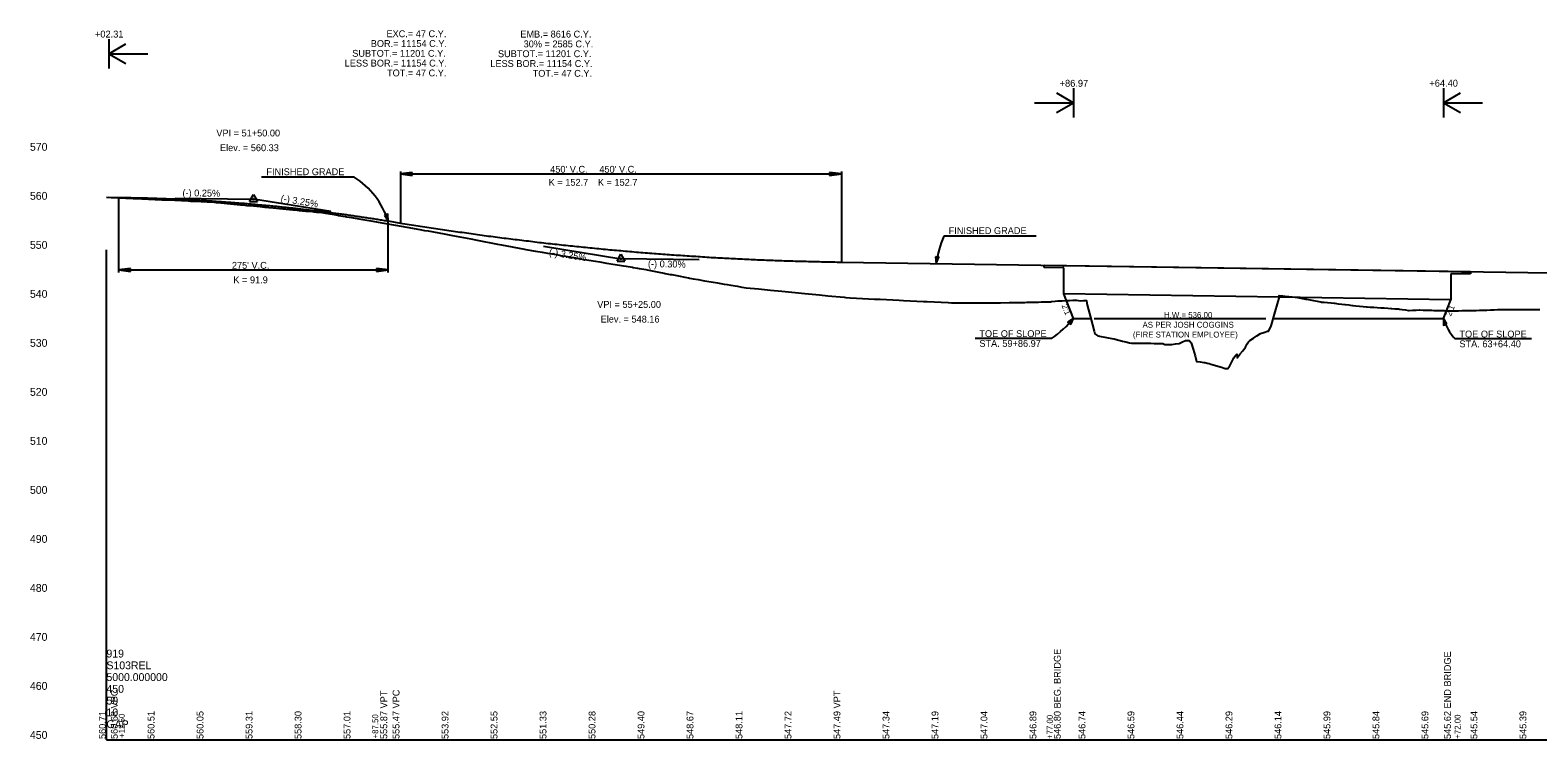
# Model space of a CAD drawing. Extents: x 49922 to 52614, y 49991 to 60509.
# Drawn here: x 49922 to 51461, y 52500 to 53224 of the extents above; entities that cross this region are included whole.
import ezdxf

# ---------------------------------------------------------------- set-up
doc = ezdxf.new("R2010")
doc.units = 0
for name, color, linetype in [('RD_DDB_ElevTX', 7, 'Continuous'), ('RD_DDB_GradeTX', 7, 'Continuous'), ('RD_DDB_Profile_EX', 7, 'Continuous'), ('RD_DDB_Profile_Lbl', 7, 'Continuous'), ('RD_DDB_Profile_PR', 7, 'Continuous'), ('RD_DDB_StripGrade', 7, 'Continuous'), ('RD_DDB_VCLbl', 7, 'Continuous'), ('RD_GPK_Profile_Cell', 7, 'Continuous'), ('RD_Sketch7', 7, 'Continuous'), ('RD_Sketch8', 7, 'Continuous'), ('RD_TX_Profile', 7, 'Continuous')]:
    doc.layers.add(name, color=color, linetype=linetype)

msp = doc.modelspace()

# ---------------------------------------------------------------- linework, layer by layer
at = {"layer": 'RD_DDB_GradeTX'}
for p, q in [((50070, 53052.7), (50150, 53051.7)), ((50146, 53049.4), (50150, 53056.3)), ((50150, 53056.3), (50154, 53049.4)), ((50229, 53038.9), (50150, 53051.7)), ((50146, 53049.4), (50154, 53049.4)), ((50446, 53003.6), (50525, 52990.8)), ((50521, 52988.5), (50525, 52995.4)), ((50525, 52995.4), (50529, 52988.5)), ((50605, 52989.6), (50525, 52990.8)), ((50521, 52988.5), (50529, 52988.5))]:
    msp.add_line(p, q, dxfattribs=at)
for centre in [(50150, 53051.7), (50525, 52990.8)]:
    msp.add_circle(centre, 0.529, dxfattribs=at)
at = {"layer": 'RD_DDB_Profile_EX'}
for points in [[(50000, 53053.7), (50004.7, 53053.4), (50027.3, 53052.4), (50029.1, 53052.3), (50049.8, 53051.4), (50052.3, 53051.3), (50053.5, 53051.2), (50056.5, 53051.1), (50063.1, 53050.8), (50069.8, 53050.5), (50076.5, 53050.1), (50077.3, 53050.1), (50077.7, 53050.1), (50083.2, 53049.8), (50085.9, 53049.7), (50089.9, 53049.5), (50096.5, 53049.2), (50102.6, 53048.8), (50103.2, 53048.8), (50109.9, 53048.4), (50111.8, 53048.3), (50113.2, 53048.2), (50116.6, 53047.9), (50123.3, 53047.2), (50130, 53046.6), (50136.7, 53045.9), (50139.3, 53045.7), (50143.3, 53045.3), (50150, 53044.7), (50156.7, 53044), (50161.6, 53043.5), (50163.4, 53043.4), (50165.7, 53043.2), (50170, 53042.8), (50176.7, 53042.1), (50183.4, 53041.4), (50186.6, 53041.1), (50190.1, 53040.8), (50192.3, 53040.6), (50196.8, 53040.2), (50203.4, 53039.5), (50210.1, 53038.9), (50211.5, 53038.7), (50214.2, 53038.5), (50216.8, 53038.2), (50219.8, 53037.9), (50223.5, 53037.3), (50230.2, 53036.2), (50236.1, 53035.3), (50236.8, 53035.1), (50243.5, 53033.9), (50244.8, 53033.7), (50250.2, 53032.8), (50259.5, 53031.3), (50269.8, 53029.4), (50283, 53027.3), (50294.8, 53025.1), (50306.4, 53023.2), (50319.8, 53020.7), (50324.6, 53019.8), (50328.3, 53019.2), (50344.6, 53016.2), (50353.2, 53014.4), (50371.8, 53011), (50378.2, 53009.7), (50399.1, 53005.8), (50403.1, 53005), (50426.5, 53000.7), (50428.1, 53000.4), (50437.7, 52998.6), (50438.3, 52998.6), (50444.7, 52997.5), (50450, 52996.6), (50456.7, 52995.4), (50462.7, 52994.4), (50463.4, 52994.3), (50468.3, 52993.5), (50470.1, 52993.1), (50476.8, 52992), (50483.4, 52990.9), (50487.6, 52990.2), (50490.1, 52989.8), (50496.8, 52988.7), (50498.9, 52988.3), (50503.5, 52987.6), (50510.2, 52986.4), (50512.5, 52986), (50516.9, 52985.3), (50523.5, 52984.3), (50527.7, 52983.6), (50530.2, 52983.2), (50536.9, 52982.1), (50537.5, 52982), (50541.9, 52981.3), (50543.6, 52981), (50544, 52980.9), (50550.3, 52979.8), (50551.6, 52979.5), (50556.9, 52978.5), (50563.6, 52977.1), (50569, 52976.1)], [(50569, 52976.1), (50570.3, 52975.9), (50575.3, 52974.9), (50577, 52974.6), (50583.7, 52973.3), (50590.3, 52972), (50594, 52971.3), (50595, 52971.1), (50597, 52970.7), (50598.6, 52970.4), (50603.9, 52969.5), (50610.4, 52968.4), (50617.1, 52967.3), (50623.7, 52966.2), (50630.4, 52965), (50633.3, 52964.6), (50637.1, 52963.9), (50643.8, 52962.8), (50648.4, 52962), (50650.7, 52961.6), (50652.7, 52961.3), (50665.5, 52960.1), (50677.7, 52958.9), (50689.1, 52957.8), (50702.7, 52956.4), (50712.7, 52955.5), (50727.7, 52954), (50736.2, 52953.1), (50752.7, 52951.5), (50754.5, 52951.3), (50758.9, 52950.9), (50765.5, 52950.6), (50783.9, 52949.7), (50789.5, 52949.5), (50808.9, 52948.5), (50813.5, 52948.3), (50833.9, 52947.3), (50837.5, 52947.2), (50859, 52946.1), (50859.3, 52946.1), (50862.3, 52945.9), (50864.8, 52946), (50887.2, 52945.9), (50895, 52946), (50912.2, 52946), (50921.2, 52946.2), (50923.2, 52946.2), (50924.8, 52946.2), (50928.4, 52946.2), (50932, 52946.3), (50935.6, 52946.3), (50937.2, 52946.3), (50939.2, 52946.4), (50942.9, 52946.5), (50946.5, 52946.6), (50950.1, 52946.7), (50951, 52946.7), (50953.7, 52946.8), (50957.3, 52946.8), (50960.9, 52946.9), (50962.2, 52947), (50963.5, 52947), (50964.5, 52947.1), (50968.1, 52947.5), (50970.8, 52947.8), (50971.7, 52947.8), (50975.4, 52948), (50979, 52948.2), (50982.6, 52948.4), (50986.2, 52948.5), (50988.7, 52948.7), (50989.8, 52948.7), (50993.6, 52948), (50997, 52948.1), (50998.7, 52948.1), (51000, 52948.2), (51000.6, 52945.5), (51001.3, 52942.5), (51004.3, 52931.1), (51007.9, 52917.1), (51008.6, 52914.3), (51011.6, 52912.1), (51015.1, 52911.4), (51018.7, 52910.8), (51022.3, 52910.1), (51025.9, 52909.4), (51028.3, 52909), (51029.5, 52908.7), (51033.1, 52907.8), (51036.8, 52906.9), (51040.4, 52906), (51044, 52905.1), (51045.9, 52904.6), (51047.6, 52904.7), (51051.2, 52904.7), (51054.8, 52904.7), (51055.6, 52904.7), (51058.4, 52904.6), (51062, 52904.6), (51065.6, 52904.6), (51069.3, 52904.5)], [(51069.3, 52904.5), (51072.9, 52904.5), (51076.5, 52904.4), (51077.9, 52904.4), (51080.1, 52903.4), (51083.8, 52903.2), (51087.3, 52903.5), (51091.1, 52903.9), (51094.7, 52904.3), (51098.2, 52905.9), (51101.3, 52907.3), (51101.8, 52907.3), (51104.8, 52907.5), (51105.4, 52906.9), (51107, 52904.9), (51109, 52898.6), (51111.1, 52891.8), (51112.4, 52886), (51116.2, 52885.5), (51119.8, 52885), (51120.7, 52884.9), (51122.4, 52884.7), (51123.4, 52884.4), (51125.3, 52883.8), (51127, 52883.3), (51130.7, 52882.2), (51134.3, 52881.2), (51137.9, 52880.1), (51141.7, 52878.9), (51144.6, 52878.7), (51145.1, 52879.4), (51145.7, 52880.3), (51148.7, 52886.2), (51150.5, 52889.7), (51152.3, 52892.2), (51153.4, 52893.6), (51153.9, 52889.7), (51155.9, 52892.6), (51156.7, 52893.6), (51159.5, 52897), (51162.5, 52900.5), (51163.2, 52901.9), (51164.2, 52903.9), (51165.6, 52906.1), (51166.2, 52906.9), (51166.8, 52907.3), (51170.4, 52909.7), (51174, 52912.1), (51177.7, 52914.5), (51181.2, 52915.7), (51184.8, 52916.8), (51185.9, 52917.1), (51186.3, 52917.2), (51188.4, 52922.3), (51188.9, 52923.5), (51192, 52934.4), (51195.7, 52947.1), (51196.6, 52950.5), (51196.8, 52953.2), (51199.3, 52953), (51200.3, 52953), (51202.9, 52952.7), (51206.5, 52952.3), (51210.1, 52951.9), (51213.1, 52951.6), (51213.7, 52951.5), (51217.3, 52950.9), (51220.1, 52950.4), (51221, 52950.2), (51223.6, 52949.7), (51224.6, 52949.6), (51228.2, 52948.9), (51231.8, 52948.3), (51235.4, 52947.6), (51239, 52946.9), (51239.4, 52946.8), (51240, 52946.7), (51242.6, 52946.5), (51246.2, 52946.1), (51249.8, 52945.8), (51253, 52945.5), (51253.4, 52945.4), (51257.1, 52944.9), (51260.7, 52944.5), (51263.6, 52944.1), (51264.3, 52944), (51267.9, 52943.7), (51269.1, 52943.6), (51271.5, 52943.3), (51272.4, 52943.2), (51275.1, 52942.9), (51278.7, 52942.5), (51282.3, 52942.1), (51285.9, 52941.7), (51286.7, 52941.7), (51289.6, 52941.5), (51293.2, 52941.3), (51296.8, 52941), (51300.4, 52940.8), (51304, 52940.6), (51307.6, 52940.3)], [(51307.6, 52940.3), (51310.6, 52940.1), (51311.2, 52940.1), (51311.6, 52940.1), (51314.8, 52939.8), (51318.5, 52939.6), (51319.4, 52939.5), (51322.1, 52939.2), (51325.7, 52938.6), (51328.8, 52938.1), (51329.4, 52938.1), (51332.9, 52938.3), (51336.5, 52938.5), (51339.7, 52938.6), (51340.1, 52938.6), (51343.7, 52938.5), (51347.3, 52938.4), (51351, 52938.3), (51352.6, 52938.3), (51354.6, 52938.2), (51358.2, 52938.1), (51361.8, 52938), (51365.4, 52937.9), (51369, 52937.8), (51372.6, 52937.7), (51376.3, 52937.6), (51379.8, 52937.8), (51383.5, 52937.9), (51386.7, 52938), (51387.1, 52938), (51390.7, 52938.1), (51394.3, 52938.1), (51397.9, 52938.2), (51401.2, 52938.3), (51401.5, 52938.3), (51405.1, 52938.4), (51408.7, 52938.5), (51412.4, 52938.7), (51416, 52938.8), (51419.6, 52938.9), (51421.9, 52939), (51422.3, 52939), (51423.2, 52939), (51426.8, 52939), (51430.4, 52939), (51434, 52939), (51437.6, 52939), (51441.2, 52939), (51442.8, 52939), (51444.9, 52939), (51447.4, 52939), (51448.5, 52939), (51452.1, 52939), (51455.7, 52939), (51459.3, 52939), (51462.9, 52938.9)]]:
    msp.add_lwpolyline(points, dxfattribs=at)
at = {"layer": 'RD_DDB_Profile_PR'}
for p, q in [((50002.3, 53053.6), (50012.5, 53053.4)), ((50287.5, 53029.4), (50300, 53027.3)), ((50750, 52987.4), (51796.9, 52971.7))]:
    msp.add_line(p, q, dxfattribs=at)
for points in [[(50012.5, 53053.4), (50018, 53053.3), (50023.5, 53053.2), (50029, 53053.1), (50034.5, 53053), (50040, 53052.9), (50045.5, 53052.7), (50051, 53052.5), (50056.5, 53052.3), (50062, 53052.1), (50067.5, 53051.9), (50073, 53051.7), (50078.5, 53051.4), (50084, 53051.1), (50089.5, 53050.8), (50095, 53050.5), (50100.5, 53050.2), (50106, 53049.9), (50111.5, 53049.5), (50117, 53049.1), (50122.5, 53048.7), (50128, 53048.3), (50133.5, 53047.9), (50139, 53047.5), (50144.5, 53047), (50150, 53046.5), (50155.5, 53046), (50161, 53045.5), (50166.5, 53045), (50172, 53044.5), (50177.5, 53043.9), (50183, 53043.3), (50188.5, 53042.8), (50194, 53042.2), (50199.5, 53041.5), (50205, 53040.9), (50210.5, 53040.2), (50216, 53039.6), (50221.5, 53038.9), (50227, 53038.2), (50232.5, 53037.5), (50238, 53036.7), (50243.5, 53036), (50249, 53035.2), (50254.5, 53034.4), (50260, 53033.6), (50265.5, 53032.8), (50271, 53032), (50276.5, 53031.1), (50282, 53030.2), (50287.5, 53029.4)], [(50300, 53027.3), (50309, 53025.9), (50318, 53024.5), (50327, 53023.1), (50336, 53021.7), (50345, 53020.4), (50354, 53019), (50363, 53017.8), (50372, 53016.5), (50381, 53015.3), (50390, 53014), (50399, 53012.9), (50408, 53011.7), (50417, 53010.6), (50426, 53009.5), (50435, 53008.4), (50444, 53007.3), (50453, 53006.3), (50462, 53005.3), (50471, 53004.4), (50480, 53003.4), (50489, 53002.5), (50498, 53001.6), (50507, 53000.7), (50516, 52999.9), (50525, 52999.1), (50534, 52998.3), (50543, 52997.5), (50552, 52996.8), (50561, 52996.1), (50570, 52995.4), (50579, 52994.8), (50588, 52994.2), (50597, 52993.6), (50606, 52993), (50615, 52992.4), (50624, 52991.9), (50633, 52991.4), (50642, 52991), (50651, 52990.5), (50660, 52990.1), (50669, 52989.7), (50678, 52989.4), (50687, 52989), (50696, 52988.7), (50705, 52988.4), (50714, 52988.2), (50723, 52988), (50732, 52987.8), (50741, 52987.6), (50750, 52987.4)]]:
    msp.add_spline(points, degree=3, dxfattribs=at)
at = {"layer": 'RD_DDB_VCLbl'}
for p, q in [((50300, 53079.8), (50300, 53027.3)), ((50312, 53078.8), (50300, 53077.3)), ((50300, 53077.3), (50750, 53077.3)), ((50300, 53077.3), (50312, 53075.8)), ((50312, 53075.8), (50312, 53078.8)), ((50750, 53077.3), (50738, 53078.8)), ((50738, 53078.8), (50738, 53075.8)), ((50738, 53075.8), (50750, 53077.3)), ((50750, 53079.8), (50750, 52987.4)), ((50012.5, 52976.9), (50012.5, 53053.4)), ((50287.5, 52976.9), (50287.5, 53029.4)), ((50024.5, 52980.9), (50012.5, 52979.4)), ((50012.5, 52979.4), (50287.5, 52979.4)), ((50012.5, 52979.4), (50024.5, 52977.9)), ((50024.5, 52977.9), (50024.5, 52980.9)), ((50287.5, 52979.4), (50275.5, 52980.9)), ((50275.5, 52980.9), (50275.5, 52977.9)), ((50287.5, 52979.4), (50275.5, 52980.9)), ((50275.5, 52980.9), (50275.5, 52977.9)), ((50275.5, 52977.9), (50287.5, 52979.4)), ((50275.5, 52977.9), (50287.5, 52979.4))]:
    msp.add_line(p, q, dxfattribs=at)
at = {"layer": 'RD_GPK_Profile_Cell'}
for q in [(50000, 53000), (52600, 52500), (50000, 52500)]:
    msp.add_line((50000, 52500), q, dxfattribs=at)
at = {"layer": 'RD_Sketch7'}
for p, q in [((50987, 52930), (50977, 52954.9)), ((51364.4, 52930), (51372, 52949)), ((50987, 52930), (51004.5, 52930)), ((51190.8, 52930), (51364.4, 52930))]:
    msp.add_line(p, q, dxfattribs=at)
at = {"layer": 'RD_Sketch8'}
for p, q in [((50957, 52984.3), (51392, 52977.8)), ((50957, 52981.8), (50957, 52984.3)), ((50977, 52981.5), (50957, 52981.8)), ((50977, 52954.9), (50977, 52981.5)), ((51392, 52975.3), (51372, 52975.6)), ((51372, 52975.6), (51372, 52949)), ((51392, 52977.8), (51392, 52975.3)), ((51372, 52949), (50977, 52954.9))]:
    msp.add_line(p, q, dxfattribs=at)
at = {"layer": 'RD_TX_Profile'}
for p, q in [((50002.3, 53215), (50002.3, 53185)), ((50002.3, 53200), (50019.6, 53210)), ((50002.3, 53200), (50019.6, 53190)), ((50002.3, 53200), (50042.3, 53200)), ((50969.6, 53160), (50987, 53150)), ((50987, 53165), (50987, 53135)), ((51364.4, 53165), (51364.4, 53135)), ((51364.4, 53150), (51381.7, 53160)), ((50947, 53150), (50987, 53150)), ((50969.6, 53140), (50987, 53150)), ((51364.4, 53150), (51381.7, 53140)), ((51364.4, 53150), (51404.4, 53150)), ((50252.8, 53074.1), (50158.2, 53074.1)), ((50948.9, 53014), (50854.4, 53014)), ((51008.1, 52930), (51183, 52930)), ((50964.5, 52909.4), (50886.6, 52909.4)), ((51454.4, 52909), (51376.4, 52909))]:
    msp.add_line(p, q, dxfattribs=at)
for points in [[(50283.7, 53035.2), (50287.5, 53029.4), (50287.1, 53036.3)], [(50845.9, 52992.8), (50846.7, 52985.9), (50849.5, 52992.3)], [(50984, 52923.7), (50987, 52930), (50981.2, 52926)], [(51367.9, 52924), (51364.4, 52930), (51364.4, 52923)]]:
    msp.add_lwpolyline(points, close=True, dxfattribs=at)
for centre, radius, start, end in [((50207.8, 53003.4), 83.8, 18.0396, 57.5215), ((50965.8, 52968.4), 120.3, 157.7492, 171.6417), ((50896, 53006.7), 119, 305.1615, 319.8853), ((51411.2, 52942.9), 48.5, 195.38, 224.2532)]:
    msp.add_arc(centre, radius, start, end, dxfattribs=at)

# ---------------------------------------------------------------- texts
at = {"layer": 'RD_DDB_ElevTX'}
for s, p in [('570', (49921.9, 53101)), ('560', (49921.9, 53051)), ('550', (49921.9, 53001)), ('540', (49921.9, 52951)), ('530', (49921.9, 52901)), ('520', (49921.9, 52851)), ('510', (49921.9, 52801)), ('500', (49921.9, 52751)), ('490', (49921.9, 52701)), ('480', (49921.9, 52651)), ('470', (49921.9, 52601)), ('460', (49921.9, 52551)), ('450', (49921.9, 52501))]:
    msp.add_text(s, height=8, dxfattribs=at).set_placement(p)
at = {"layer": 'RD_DDB_GradeTX'}
for s, rotation, p in [('(-) 0.25%', 359.2719, (50077.5, 53054.6)), ('(-) 3.25%', 350.7803, (50177.4, 53049.2)), ('(-) 3.25%', 350.7803, (50451.2, 52994.5)), ('(-) 0.30%', 359.1406, (50552.5, 52982.3))]:
    msp.add_text(s, height=7, rotation=rotation, dxfattribs=at).set_placement(p)
at = {"layer": 'RD_DDB_Profile_Lbl'}
for s, p in [('VPI = 51+50.00', (50112.1, 53115.6)), ('Elev. = 560.33', (50115.8, 53100.6)), ('VPI = 55+25.00', (50500.8, 52940.7)), ('Elev. = 548.16', (50504.3, 52925.7))]:
    msp.add_text(s, height=7, dxfattribs=at).set_placement(p)
at = {"layer": 'RD_DDB_StripGrade'}
for s, p in [('546.80 BEG. BRIDGE', (50973.8, 52500.8)), ('545.62 END BRIDGE', (51372, 52500.8)), ('560.68 VPC', (50011.5, 52500.8)), ('555.87 VPT', (50286.5, 52500.8)), ('555.47 VPC', (50299, 52500.8)), ('547.49 VPT', (50749, 52500.8)), ('560.71', (49999.3, 52500.8)), ('560.51', (50049, 52500.8)), ('560.05', (50099, 52500.8)), ('559.31', (50149, 52500.8)), ('558.30', (50199, 52500.8)), ('557.01', (50249, 52500.8)), ('555.47', (50299, 52500.8)), ('553.92', (50349, 52500.8)), ('552.55', (50399, 52500.8)), ('551.33', (50449, 52500.8)), ('550.28', (50499, 52500.8)), ('549.40', (50549, 52500.8)), ('548.67', (50599, 52500.8)), ('548.11', (50649, 52500.8)), ('547.72', (50699, 52500.8)), ('547.49', (50749, 52500.8)), ('547.34', (50799, 52500.8)), ('547.19', (50849, 52500.8)), ('547.04', (50899, 52500.8)), ('546.89', (50949, 52500.8)), ('546.74', (50999, 52500.8)), ('546.59', (51049, 52500.8)), ('546.44', (51099, 52500.8)), ('546.29', (51149, 52500.8)), ('546.14', (51199, 52500.8)), ('545.99', (51249, 52500.8)), ('545.84', (51299, 52500.8)), ('545.69', (51349, 52500.8)), ('545.54', (51399, 52500.8)), ('545.39', (51449, 52500.8))]:
    msp.add_text(s, height=7, rotation=90, dxfattribs=at).set_placement(p)
at = {"layer": 'RD_DDB_VCLbl'}
for s, p in [("450' V.C.", (50452.8, 53078.6)), ("450' V.C.", (50503, 53078.6)), ('K = 152.7', (50451.3, 53065.3)), ('K = 152.7', (50501.5, 53065.3)), ("275' V.C.", (50128, 52980.6)), ('K = 91.9', (50129.5, 52965.8))]:
    msp.add_text(s, height=7, dxfattribs=at).set_placement(p)
at = {"layer": 'RD_GPK_Profile_Cell'}
for s, p in [('919', (50000, 52584)), ('S103REL', (50000, 52572)), ('5000.000000', (50000, 52560)), ('450', (50000, 52548)), ('50', (50000, 52536)), ('10', (50000, 52524)), ('GAP', (50000, 52512))]:
    msp.add_text(s, height=8, dxfattribs=at).set_placement(p)
at = {"layer": 'RD_TX_Profile'}
for s, height, p in [('+02.31', 7.06, (49988.2, 53216.5)), ('EXC.= 47 C.Y.', 7, (50285.7, 53216.9)), ('EMB.= 8616 C.Y.', 7, (50422.3, 53216.5)), ('BOR.= 11154 C.Y.', 7, (50269.7, 53206.9)), ('30% = 2585 C.Y.', 7, (50425.7, 53206.5)), ('LESS BOR.= 11154 C.Y.', 7, (50243.1, 53186.9)), ('SUBTOT.= 11201 C.Y.', 7, (50250.8, 53196.9)), ('LESS BOR.= 11154 C.Y.', 7, (50391.7, 53186.5)), ('SUBTOT.= 11201 C.Y.', 7, (50399.5, 53196.5)), ('TOT.= 47 C.Y.', 7, (50286.3, 53176.9)), ('TOT.= 47 C.Y.', 7, (50434.9, 53176.5)), ('+86.97', 7.06, (50972.7, 53166.3)), ('+64.40', 7.06, (51350, 53166.4)), ('FINISHED GRADE', 7, (50163.2, 53076.1)), ('FINISHED GRADE', 7, (50859.4, 53016)), ('H.W.= 536.00', 6, (51079.2, 52930.5)), ('TOE OF SLOPE', 7, (50890.8, 52910.9)), ('(FIRE STATION EMPLOYEE)', 6, (51047.5, 52910.5)), ('AS PER JOSH COGGINS', 6, (51057.3, 52920.5)), ('TOE OF SLOPE', 7, (51380.7, 52910.5)), ('STA. 59+86.97', 7, (50890.8, 52900.9)), ('STA. 63+64.40', 7, (51380.7, 52900.5))]:
    msp.add_text(s, height=height, dxfattribs=at).set_placement(p)
for s, rotation, p in [('2:1', 291.8014, (50974.6, 52943.1)), ('2:1', 68.1986, (51372, 52931.7)), ('+12.50', 90, (50018.6, 52501.9)), ('+87.50', 90, (50277.3, 52501.4)), ('+77.00', 90, (50965.6, 52500.8)), ('+72.00', 90, (51381.8, 52501.1))]:
    msp.add_text(s, height=6, rotation=rotation, dxfattribs=at).set_placement(p)

doc.saveas('drawing.dxf')
